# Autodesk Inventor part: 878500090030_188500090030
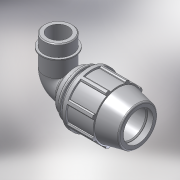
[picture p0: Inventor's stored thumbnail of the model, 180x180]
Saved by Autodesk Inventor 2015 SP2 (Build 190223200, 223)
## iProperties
Created: 2017-02
Part Number: 878500090030_188500090030
Material: PVC-Piping
Description: PLASSON 90° ELBOW MALE ADAPTOR 90-3"
Document SubType Name: Modeling
Designer: KIM
Mass: 92.6774 g
Surface Area: 199.44 cm^2
Volume: 66.1981 cm^3
Density: 1.4 g/cm^3
Appearance: Smooth - White
Author: KIM
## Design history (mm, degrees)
derived "87850.ipt"
feature "Solid1::87850.ipt"
tag "TaggingFeature1"
body "Solid1"
other parameters: "d4" = 19.33333, "d5" = 58, "d7" = 152, "d9" = 33.14286, "d11" = 7.73333, "d13" = 120 deg, "d14" = 108, "d15" = 12 deg, "d16" = 132.24, "d18" = 4.5, "d19" = 35 deg, "d20" = 17.5 deg, "d21" = 141.36, "d23" = 0, "d25" = 360 deg, "d27" = 3.04, "d33" = 1.8, "d42" = 85.84, "d43" = 4.56, "d46" = 2.7, "d51" = 232, "d68" = 15.46667, "d73" = 87.884, "d74" = 33, "d75" = 101.0666, "d76" = 61.5188, "d77" = 36.3, "d79" = 35.1536, "d80" = 2.63652, "d83" = 0, "d84" = 0, "d91" = 114, "d93" = 164, "d94" = 87.884, "d95" = 61.5188, "d96" = 15.46667, "d97" = 50 deg, "d98" = 3.86667, "d99" = 128.2728, "d100" = 3.86667, "d101" = 3.86667, "d102" = 10.13333, "d103" = 0, "E_" = 152, "A_" = 232, "l_" = 164, "l_2" = 33, "G_" = 87.884
